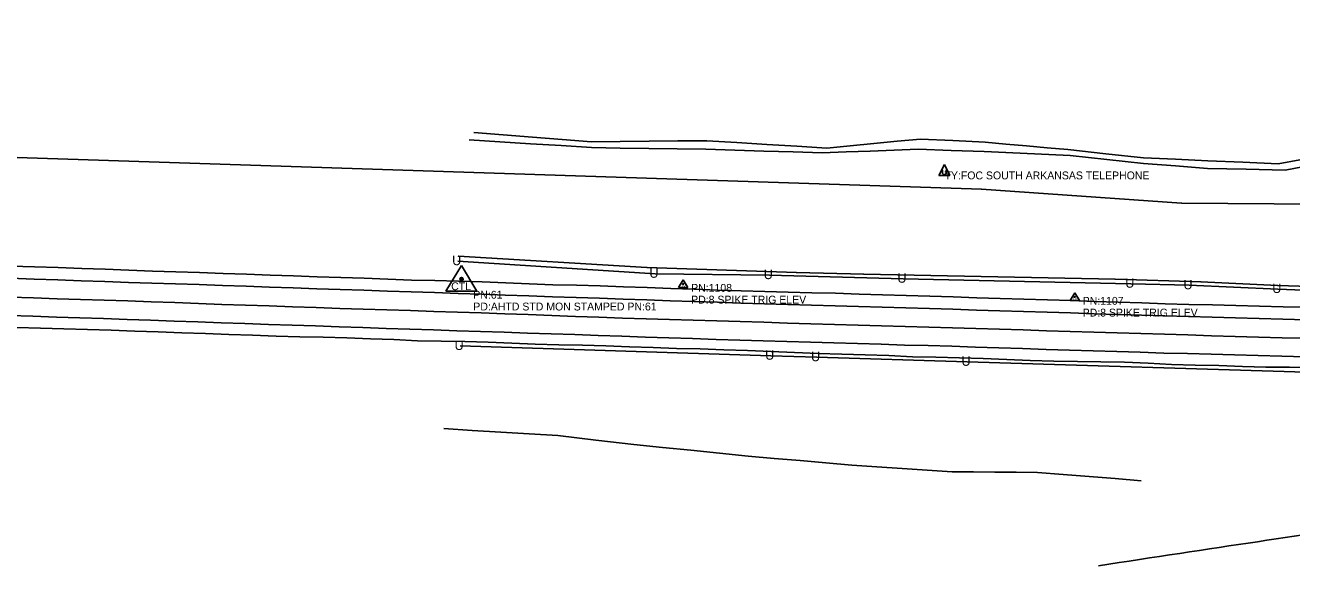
# Model space of a CAD drawing. Extents: x 976456 to 985170, y 1525951 to 1527080.
# Drawn here: x 981619 to 982425, y 1526205 to 1526549 of the extents above; entities that cross this region are included whole.
import ezdxf

# ---------------------------------------------------------------- set-up
doc = ezdxf.new("R2010")
doc.units = 0
for name, color, linetype in [('Default', 7, 'Continuous'), ('S_DITCHLINE', 7, 'Continuous'), ('S_EDGE_PAVEMENT', 7, 'Continuous'), ('S_FIBER_OPTIC_CABLE', 7, 'Continuous'), ('S_PAVEMENT_CROWN', 7, 'Continuous'), ('S_PRIMARY_CTL', 7, 'Continuous'), ('S_PRIMARY_CTL_ANNOT', 7, 'Continuous'), ('S_SECONDARY_CTL', 7, 'Continuous'), ('S_SECONDARY_CTL_ANNOT', 7, 'Continuous'), ('S_SHOULDER', 7, 'Continuous'), ('S_UNDERGROUND_CABLE', 7, 'Continuous'), ('S_UTILITY_POLE_ANNOT', 7, 'Continuous'), ('S_UTL_PT_SYM', 7, 'Continuous')]:
    doc.layers.add(name, color=color, linetype=linetype)

msp = doc.modelspace()

# ---------------------------------------------------------------- linework, layer by layer
at = {"layer": 'S_DITCHLINE'}
for points in [[(982442.41, 1526460.73), (982420.45, 1526456.65), (982395.72, 1526457.18), (982370.99, 1526457.71), (982350.63, 1526459.25), (982330.27, 1526460.79), (982306.98, 1526463.38), (982283.69, 1526465.96), (982270, 1526466.56), (982256.31, 1526467.17), (982242.62, 1526467.77), (982228.93, 1526468.37), (982207.93, 1526469.16), (982186.93, 1526469.95), (982171.67, 1526469.34), (982156.4, 1526468.74), (982141.13, 1526468.14), (982125.87, 1526467.54), (982107.33, 1526468.14), (982088.8, 1526468.74), (982070.27, 1526469.34), (982051.74, 1526469.94), (982033.59, 1526470.18), (982015.45, 1526470.42), (981997.3, 1526470.66), (981979.15, 1526470.9), (981959.7, 1526472.16), (981940.24, 1526473.42), (981920.79, 1526474.67), (981901.33, 1526475.93)], [(982429.78, 1526463.11), (982415.96, 1526460.65), (982393.56, 1526461.6), (982371.16, 1526462.55), (982350.73, 1526463.5), (982330.3, 1526464.45), (982306.26, 1526467.03), (982282.21, 1526469.61), (982269.06, 1526470.79), (982255.9, 1526471.97), (982242.74, 1526473.15), (982229.58, 1526474.32), (982209.04, 1526475.34), (982188.49, 1526476.36), (982173.56, 1526474.93), (982158.63, 1526473.49), (982143.7, 1526472.06), (982128.77, 1526470.62), (982109.67, 1526471.8), (982090.57, 1526472.97), (982071.48, 1526474.14), (982052.38, 1526475.32), (982034.04, 1526475.14), (982015.7, 1526474.95), (981997.35, 1526474.77), (981979.01, 1526474.59), (981960.32, 1526476.07), (981941.62, 1526477.56), (981922.93, 1526479.04), (981904.24, 1526480.53)], [(982328.79, 1526258.88), (982312.28, 1526260.21), (982295.78, 1526261.55), (982279.28, 1526262.88), (982262.78, 1526264.22), (982249.24, 1526264.31), (982235.7, 1526264.4), (982222.16, 1526264.5), (982208.61, 1526264.59), (982192.65, 1526265.65), (982176.69, 1526266.72), (982160.73, 1526267.78), (982144.77, 1526268.84), (982128.25, 1526270.27), (982111.74, 1526271.7), (982095.22, 1526273.12), (982078.71, 1526274.55), (982060.54, 1526276.4), (982042.37, 1526278.26), (982024.2, 1526280.11), (982006.03, 1526281.96), (981981.81, 1526284.78), (981957.58, 1526287.6), (981939.45, 1526288.71), (981921.31, 1526289.82), (981903.18, 1526290.93), (981885.04, 1526292.04)]]:
    msp.add_lwpolyline(points, dxfattribs=at)
at = {"layer": 'S_EDGE_PAVEMENT'}
for points in [[(981609.44, 1526387.73), (981624.43, 1526387.21), (981639.42, 1526386.72), (981654.41, 1526386.18), (981669.4, 1526385.62), (981684.39, 1526385.13), (981699.39, 1526384.67), (981714.38, 1526384.2), (981729.37, 1526383.69), (981729.37, 1526383.69), (981744.36, 1526383.14), (981759.28, 1526382.65), (981774.27, 1526382.09), (981789.27, 1526381.59), (981804.26, 1526381.11), (981804.26, 1526381.11), (981819.25, 1526380.64), (981834.24, 1526380.17), (981849.23, 1526379.62), (981849.23, 1526379.62), (981864.22, 1526379.06), (981864.22, 1526379.06), (981879.22, 1526378.64), (981894.21, 1526378.12), (981909.2, 1526377.58), (981924.24, 1526377.02), (981939.23, 1526376.48), (981954.22, 1526375.95), (981969.22, 1526375.6), (981984.21, 1526375.06), (981999.2, 1526374.52), (982014.19, 1526373.99), (982029.18, 1526373.47), (982044.17, 1526372.98), (982044.17, 1526372.98), (982059.16, 1526372.44), (982074.08, 1526371.97), (982089.08, 1526371.48), (982104.07, 1526371.06), (982104.07, 1526371.06), (982119.07, 1526370.68), (982134.06, 1526370.25), (982149.05, 1526369.79), (982164.05, 1526369.38), (982179.04, 1526368.93), (982194.04, 1526368.51), (982209.03, 1526368.05), (982224.02, 1526367.49), (982238.98, 1526367.04), (982253.98, 1526366.65), (982253.98, 1526366.65), (982268.97, 1526366.16), (982283.96, 1526365.72), (982298.95, 1526365.22), (982313.95, 1526364.78), (982328.94, 1526364.29), (982343.93, 1526363.82), (982343.93, 1526363.82), (982358.93, 1526363.35), (982373.9, 1526362.94), (982388.89, 1526362.54), (982403.89, 1526362.2), (982418.88, 1526361.81), (982433.88, 1526361.38)], [(981608.57, 1526364.09), (981623.56, 1526363.57), (981638.55, 1526363.04), (981653.54, 1526362.49), (981668.53, 1526362.06), (981668.53, 1526362.06), (981683.53, 1526361.6), (981698.52, 1526361.06), (981713.51, 1526360.5), (981728.5, 1526360), (981743.49, 1526359.47), (981758.53, 1526358.92), (981773.52, 1526358.36), (981788.52, 1526357.86), (981803.51, 1526357.41), (981818.5, 1526356.9), (981833.49, 1526356.35), (981848.48, 1526355.85), (981848.48, 1526355.85), (981863.47, 1526355.33), (981863.47, 1526355.33), (981878.47, 1526354.87), (981893.46, 1526354.4), (981908.45, 1526353.92), (981923.4, 1526353.38), (981938.39, 1526352.82), (981953.38, 1526352.32), (981968.37, 1526351.86), (981983.36, 1526351.35), (981998.35, 1526350.84), (982013.34, 1526350.32), (982028.34, 1526349.83), (982043.33, 1526349.34), (982058.32, 1526348.81), (982073.37, 1526348.34), (982073.37, 1526348.34), (982088.36, 1526347.9), (982088.36, 1526347.9), (982103.36, 1526347.47), (982118.35, 1526347.04), (982133.34, 1526346.62), (982133.34, 1526346.62), (982148.34, 1526346.17), (982163.33, 1526345.71), (982178.33, 1526345.27), (982193.32, 1526344.87), (982193.32, 1526344.87), (982208.32, 1526344.48), (982223.31, 1526344), (982238.32, 1526343.49), (982238.32, 1526343.49), (982253.31, 1526342.96), (982253.31, 1526342.96), (982268.31, 1526342.51), (982268.31, 1526342.51), (982283.3, 1526342.08), (982298.29, 1526341.59), (982313.29, 1526341.19), (982313.29, 1526341.19), (982328.28, 1526340.72), (982343.27, 1526340.18), (982358.27, 1526339.78), (982373.28, 1526339.37), (982373.28, 1526339.37), (982388.28, 1526338.96), (982403.27, 1526338.58), (982418.27, 1526338.21), (982433.26, 1526337.82)]]:
    msp.add_lwpolyline(points, dxfattribs=at)
at = {"layer": 'S_FIBER_OPTIC_CABLE'}
for p, q in [((982227.16, 1526444.43), (979068.74, 1526548.75)), ((982354.59, 1526435.59), (982227.16, 1526444.43)), ((982455.93, 1526434.73), (982354.59, 1526435.59)), ((982014.28, 1526394.66), (981894.37, 1526401.76)), ((982109.42, 1526391.32), (982014.28, 1526394.66)), ((982152.27, 1526390.38), (982109.42, 1526391.32)), ((982312.22, 1526387.26), (982152.27, 1526390.38)), ((982366.87, 1526385.5), (982312.22, 1526387.26)), ((982415.76, 1526383.16), (982366.87, 1526385.5)), ((982480.84, 1526381.04), (982415.76, 1526383.16))]:
    msp.add_line(p, q, dxfattribs=at)
msp.add_open_spline([(983038.02, 1526271.95), (982776.59, 1526257.91), (982699.02, 1526265.54), (982301.76, 1526204.82)], degree=2, dxfattribs=at)
at = {"layer": 'S_PAVEMENT_CROWN'}
msp.add_lwpolyline([(981609, 1526375.76), (981623.99, 1526375.25), (981623.99, 1526375.25), (981638.98, 1526374.74), (981653.97, 1526374.27), (981653.97, 1526374.27), (981668.97, 1526373.81), (981668.97, 1526373.81), (981683.96, 1526373.33), (981683.96, 1526373.33), (981698.95, 1526372.78), (981713.94, 1526372.31), (981728.93, 1526371.75), (981728.93, 1526371.75), (981743.92, 1526371.1), (981743.92, 1526371.1), (981758.9, 1526370.66), (981758.9, 1526370.66), (981773.9, 1526370.25), (981773.9, 1526370.25), (981788.89, 1526369.59), (981803.88, 1526369.11), (981803.88, 1526369.11), (981818.87, 1526368.59), (981833.86, 1526368.1), (981833.86, 1526368.1), (981848.85, 1526367.63), (981848.85, 1526367.63), (981863.85, 1526367.15), (981863.85, 1526367.15), (981878.84, 1526366.67), (981878.84, 1526366.67), (981893.83, 1526366.2), (981893.83, 1526366.2), (981908.82, 1526365.66), (981923.82, 1526365.13), (981938.81, 1526364.6), (981953.8, 1526364.06), (981968.79, 1526363.51), (981968.79, 1526363.51), (981983.78, 1526362.98), (981998.77, 1526362.44), (982013.76, 1526361.95), (982028.76, 1526361.6), (982043.75, 1526361.03), (982058.74, 1526360.61), (982073.73, 1526360.17), (982073.73, 1526360.17), (982088.72, 1526359.8), (982103.71, 1526359.28), (982103.71, 1526359.28), (982118.71, 1526358.82), (982133.7, 1526358.36), (982133.7, 1526358.36), (982148.69, 1526357.92), (982163.69, 1526357.46), (982163.69, 1526357.46), (982178.68, 1526357), (982193.68, 1526356.65), (982208.67, 1526356.17), (982223.66, 1526355.7), (982223.66, 1526355.7), (982238.65, 1526355.26), (982238.65, 1526355.26), (982253.65, 1526354.84), (982268.64, 1526354.35), (982283.63, 1526353.88), (982298.62, 1526353.46), (982313.62, 1526352.93), (982313.62, 1526352.93), (982328.61, 1526352.52), (982328.61, 1526352.52), (982343.6, 1526352.1), (982358.6, 1526351.68), (982373.59, 1526351.19), (982373.59, 1526351.19), (982388.58, 1526350.76), (982403.58, 1526350.33), (982418.57, 1526349.94), (982418.57, 1526349.94), (982433.57, 1526349.58)], dxfattribs=at)
at = {"layer": 'S_PRIMARY_CTL'}
for p, q in [((981896.36, 1526395.96), (981886.33, 1526379.45)), ((981896.36, 1526395.96), (981906.19, 1526379.45)), ((981886.33, 1526379.45), (981906.19, 1526379.45))]:
    msp.add_line(p, q, dxfattribs=at)
for radius in [1.04, 0.609, 0.344]:
    msp.add_circle((981896.36, 1526387.26), radius, dxfattribs=at)
at = {"layer": 'S_SECONDARY_CTL'}
for p, q in [((982037.47, 1526386.76), (982034.46, 1526381.81)), ((982037.47, 1526386.76), (982040.42, 1526381.81)), ((982034.46, 1526381.81), (982040.42, 1526381.81)), ((982286.6, 1526378.51), (982283.59, 1526373.55)), ((982286.6, 1526378.51), (982289.55, 1526373.55)), ((982283.59, 1526373.55), (982289.55, 1526373.55))]:
    msp.add_line(p, q, dxfattribs=at)
for centre, radius in [((982037.47, 1526384.15), 0.311), ((982037.47, 1526384.15), 0.183), ((982037.47, 1526384.15), 0.103), ((982286.6, 1526375.9), 0.311), ((982286.6, 1526375.9), 0.183), ((982286.6, 1526375.9), 0.103)]:
    msp.add_circle(centre, radius, dxfattribs=at)
at = {"layer": 'S_SHOULDER'}
for points in [[(981609.73, 1526395.48), (981624.72, 1526394.96), (981639.71, 1526394.53), (981654.71, 1526394.03), (981669.7, 1526393.48), (981684.69, 1526392.94), (981699.68, 1526392.37), (981714.67, 1526391.89), (981729.66, 1526391.39), (981744.65, 1526390.82), (981759.53, 1526390.33), (981774.52, 1526389.74), (981789.51, 1526389.23), (981804.5, 1526388.66), (981819.49, 1526388.19), (981834.48, 1526387.72), (981849.48, 1526387.24), (981864.46, 1526386.6), (981879.46, 1526386.35), (981894.46, 1526385.94), (981909.45, 1526385.39), (981924.52, 1526384.79), (981939.51, 1526384.23), (981954.5, 1526383.64), (981969.5, 1526383.36), (981984.49, 1526382.86), (981999.48, 1526382.33), (982014.47, 1526381.82), (982029.47, 1526381.31), (982044.46, 1526380.81), (982059.45, 1526380.25), (982074.33, 1526379.85), (982089.32, 1526379.39), (982104.31, 1526378.97), (982119.31, 1526378.56), (982134.3, 1526378.18), (982149.3, 1526377.72), (982164.29, 1526377.31), (982179.28, 1526376.86), (982194.28, 1526376.44), (982209.27, 1526375.98), (982224.26, 1526375.33), (982239.2, 1526374.86), (982254.2, 1526374.44), (982269.19, 1526373.96), (982284.18, 1526373.51), (982299.17, 1526372.95), (982314.17, 1526372.54), (982329.16, 1526372.05), (982344.15, 1526371.55), (982359.14, 1526371.08), (982374.11, 1526370.91), (982389.1, 1526370.44), (982404.09, 1526370.09), (982419.09, 1526369.66), (982434.09, 1526369.34)], [(981613.42, 1526356.43), (981628.42, 1526356.09), (981643.41, 1526355.56), (981658.41, 1526355.24), (981673.4, 1526354.63), (981688.39, 1526354.12), (981703.38, 1526353.56), (981718.37, 1526353.01), (981733.36, 1526352.57), (981748.35, 1526352.05), (981763.44, 1526351.5), (981778.43, 1526350.95), (981793.42, 1526350.56), (981808.42, 1526350.3), (981823.41, 1526349.75), (981838.4, 1526349.19), (981853.39, 1526348.72), (981868.38, 1526347.93), (981883.38, 1526347.76), (981898.38, 1526347.47), (981913.3, 1526347.02), (981928.28, 1526346.42), (981943.28, 1526345.89), (981958.27, 1526345.36), (981973.27, 1526345.15), (981988.26, 1526344.72), (982003.25, 1526344.09), (982018.24, 1526343.69), (982033.23, 1526343.14), (982048.23, 1526342.87), (982063.22, 1526342.25), (982078.3, 1526341.7), (982093.29, 1526341.14), (982108.28, 1526340.5), (982123.27, 1526339.93), (982138.27, 1526339.49), (982153.26, 1526339), (982168.25, 1526338.53), (982183.23, 1526337.82), (982198.23, 1526337.56), (982213.23, 1526337.2), (982228.22, 1526336.64), (982243.25, 1526336), (982258.24, 1526335.41), (982273.23, 1526335.04), (982288.23, 1526334.69), (982303.23, 1526334.63), (982318.23, 1526334.29), (982333.22, 1526333.69), (982348.2, 1526332.86), (982363.2, 1526332.45), (982378.23, 1526332.23), (982393.22, 1526331.58), (982408.21, 1526331.24), (982423.22, 1526331.21), (982438.21, 1526330.64)]]:
    msp.add_lwpolyline(points, dxfattribs=at)
at = {"layer": 'S_UNDERGROUND_CABLE'}
for p, q in [((982203.69, 1526460.25), (982200.16, 1526453.15)), ((982203.69, 1526460.25), (982207.17, 1526453.15)), ((982200.16, 1526453.15), (982207.17, 1526453.15)), ((982202.49, 1526454.39), (982202.49, 1526456.84)), ((982203.11, 1526453.74), (982202.49, 1526454.39)), ((982204.31, 1526453.74), (982203.11, 1526453.74)), ((982204.85, 1526454.39), (982204.31, 1526453.74)), ((982204.85, 1526456.84), (982204.85, 1526454.39)), ((982019.53, 1526390.62), (981894.04, 1526398.62)), ((982092.3, 1526389.76), (982019.53, 1526390.62)), ((982177.34, 1526387.45), (982092.3, 1526389.76)), ((982322.34, 1526384.28), (982177.34, 1526387.45)), ((982359.38, 1526383.29), (982322.34, 1526384.28)), ((982415.84, 1526380.92), (982359.38, 1526383.29)), ((982487.89, 1526377.93), (982415.84, 1526380.92)), ((982093.22, 1526338.46), (981895.57, 1526344.65)), ((982122.41, 1526337.5), (982093.22, 1526338.46)), ((982218.12, 1526334.59), (982122.41, 1526337.5)), ((982440.57, 1526327.81), (982218.12, 1526334.59))]:
    msp.add_line(p, q, dxfattribs=at)
at = {"layer": 'S_UTL_PT_SYM'}
for points in [[(982227.16, 1526444.43), (982227.16, 1526444.48), (982227.16, 1526444.43), (982227.11, 1526444.43), (982227.16, 1526444.43), (982227.16, 1526444.38), (982227.16, 1526444.43), (982227.21, 1526444.43)], [(982354.59, 1526435.59), (982354.59, 1526435.64), (982354.59, 1526435.59), (982354.54, 1526435.59), (982354.59, 1526435.59), (982354.59, 1526435.54), (982354.59, 1526435.59), (982354.64, 1526435.59)], [(981894.37, 1526401.76), (981894.37, 1526401.81), (981894.37, 1526401.76), (981894.32, 1526401.76), (981894.37, 1526401.76), (981894.37, 1526401.71), (981894.37, 1526401.76), (981894.42, 1526401.76)], [(982014.28, 1526394.66), (982014.28, 1526394.71), (982014.28, 1526394.66), (982014.23, 1526394.66), (982014.28, 1526394.66), (982014.28, 1526394.61), (982014.28, 1526394.66), (982014.33, 1526394.66)], [(982109.42, 1526391.32), (982109.42, 1526391.37), (982109.42, 1526391.32), (982109.37, 1526391.32), (982109.42, 1526391.32), (982109.42, 1526391.27), (982109.42, 1526391.32), (982109.47, 1526391.32)], [(982152.27, 1526390.38), (982152.27, 1526390.43), (982152.27, 1526390.38), (982152.22, 1526390.38), (982152.27, 1526390.38), (982152.27, 1526390.33), (982152.27, 1526390.38), (982152.32, 1526390.38)], [(982312.22, 1526387.26), (982312.22, 1526387.31), (982312.22, 1526387.26), (982312.17, 1526387.26), (982312.22, 1526387.26), (982312.22, 1526387.21), (982312.22, 1526387.26), (982312.27, 1526387.26)], [(982366.87, 1526385.5), (982366.87, 1526385.55), (982366.87, 1526385.5), (982366.82, 1526385.5), (982366.87, 1526385.5), (982366.87, 1526385.45), (982366.87, 1526385.5), (982366.92, 1526385.5)], [(982415.76, 1526383.16), (982415.76, 1526383.21), (982415.76, 1526383.16), (982415.71, 1526383.16), (982415.76, 1526383.16), (982415.76, 1526383.11), (982415.76, 1526383.16), (982415.81, 1526383.16)]]:
    msp.add_lwpolyline(points, dxfattribs=at)

# ---------------------------------------------------------------- texts
at = {"layer": 'Default'}
for p in [(981890.41, 1526396.07), (982015.9, 1526388.08), (982088.67, 1526387.22), (982173.71, 1526384.91), (982318.71, 1526381.74), (982355.75, 1526380.75), (982412.21, 1526378.37), (981891.94, 1526342.1), (982089.59, 1526335.91), (982118.78, 1526334.95), (982214.49, 1526332.05)]:
    msp.add_text('U', height=6, rotation=360, dxfattribs=at).set_placement(p)
at = {"layer": 'S_PRIMARY_CTL'}
msp.add_text('CTL', height=5, rotation=360, dxfattribs=at).set_placement((981889.78, 1526380.18))
at = {"layer": 'S_PRIMARY_CTL_ANNOT'}
for s, p in [('PN:61', (981903.86, 1526374.76)), ('PD:AHTD STD MON STAMPED PN:61', (981903.86, 1526367.26))]:
    msp.add_text(s, height=5, dxfattribs=at).set_placement(p)
at = {"layer": 'S_SECONDARY_CTL'}
for p in [(982036.26, 1526382.14), (982285.4, 1526373.89)]:
    msp.add_text('TV', height=1.5, rotation=360, dxfattribs=at).set_placement(p)
at = {"layer": 'S_SECONDARY_CTL_ANNOT'}
for s, p in [('PN:1108', (982042.47, 1526379.15)), ('PD:8 SPIKE TRIG ELEV', (982042.47, 1526371.65)), ('PN:1107', (982291.6, 1526370.9)), ('PD:8 SPIKE TRIG ELEV', (982291.6, 1526363.4))]:
    msp.add_text(s, height=5, dxfattribs=at).set_placement(p)
at = {"layer": 'S_UTILITY_POLE_ANNOT'}
msp.add_text('TY:FOC SOUTH ARKANSAS TELEPHONE', height=5, dxfattribs=at).set_placement((982203.69, 1526450.71))

doc.saveas('drawing.dxf')
